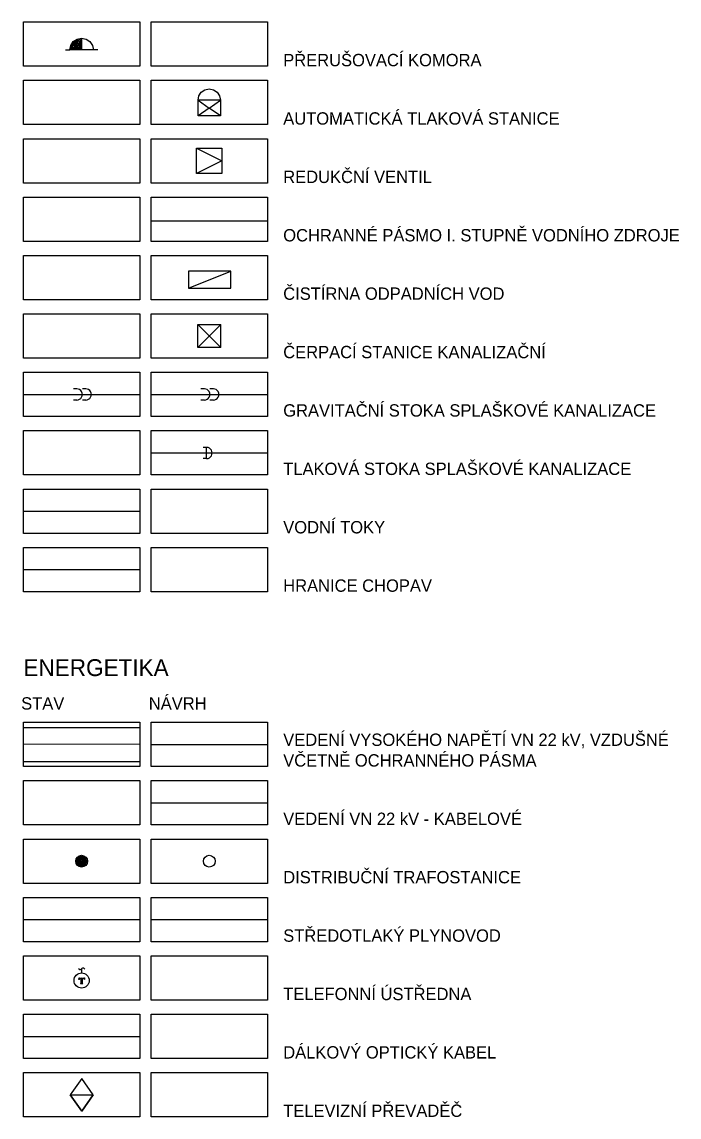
# Model space of a CAD drawing. Extents: x -439236 to -436242, y -1130161 to -1121098.
# Drawn here: x -439126 to -438541, y -1130047 to -1129071 of the extents above; entities that cross this region are included whole.
import ezdxf

# ---------------------------------------------------------------- set-up
doc = ezdxf.new("R2010")
doc.units = 0
for name, color, linetype in [('13861012_venkovní vedení elektrické sítě VN 1-35 kV_Stav', 7, 'Continuous'), ('14250012_plynovod STL_Stav', 7, 'Continuous'), ('14801013_OP vedení elektrické sítě_Stav', 7, 'Continuous'), ('Trafostanice', 7, 'Continuous'), ('Vrstva 1', 7, 'Continuous'), ('Vrstva 10', 7, 'Continuous'), ('Vrstva 11', 7, 'Continuous'), ('Vrstva 13', 7, 'Continuous'), ('Vrstva 19', 7, 'Continuous'), ('Vrstva 27', 7, 'Continuous'), ('Vrstva 33', 7, 'Continuous'), ('Vrstva 34', 7, 'Continuous'), ('Vrstva 36', 7, 'Continuous'), ('Vrstva 39', 7, 'Continuous'), ('Vrstva 46', 7, 'Continuous'), ('Vrstva 57', 7, 'Continuous'), ('Vrstva 58', 7, 'Continuous'), ('Vrstva 59', 7, 'Continuous'), ('WT - vodni a vodnich toku', 7, 'Continuous')]:
    doc.layers.add(name, color=color, linetype=linetype)

msp = doc.modelspace()

# ---------------------------------------------------------------- linework, layer by layer
at = {"layer": '13861012_venkovní vedení elektrické sítě VN 1-35 kV_Stav'}
msp.add_line((-439011.28, -1129715.01), (-438907.66, -1129715.01), dxfattribs=at)
msp.add_lwpolyline([(-439021.28, -1129714.91), (-439124.89, -1129715.12)], dxfattribs=at)
at = {"layer": '14250012_plynovod STL_Stav'}
for p, q in [((-439124.89, -1129871.07), (-439021.28, -1129871.07)), ((-439011.28, -1129871.07), (-438907.66, -1129871.07))]:
    msp.add_line(p, q, dxfattribs=at)
at = {"layer": '14801013_OP vedení elektrické sítě_Stav'}
for p, q in [((-439124.89, -1129699.91), (-439021.28, -1129699.91)), ((-439021.28, -1129730.5), (-439124.89, -1129730.5))]:
    msp.add_line(p, q, dxfattribs=at)
at = {"layer": 'Trafostanice'}
for radius in [5.25, 4.55, 3.85, 3.15, 2.45, 1.75, 1.05, 0.35]:
    msp.add_circle((-439073.09, -1129819.05), radius, dxfattribs=at)
at = {"layer": 'Vrstva 1'}
for points in [[(-439124.89, -1129071.38), (-439021.28, -1129071.38), (-439021.28, -1129071.38), (-439021.28, -1129110.89), (-439124.89, -1129110.89)], [(-439011.28, -1129071.38), (-438907.66, -1129071.38), (-438907.66, -1129110.89), (-439011.28, -1129110.89)], [(-439124.89, -1129123.4), (-439021.28, -1129123.4), (-439021.28, -1129123.4), (-439021.28, -1129162.91), (-439124.89, -1129162.91)], [(-439011.28, -1129123.4), (-438907.66, -1129123.4), (-438907.66, -1129162.91), (-439011.28, -1129162.91)], [(-439124.89, -1129175.42), (-439021.28, -1129175.42), (-439021.28, -1129175.42), (-439021.28, -1129214.92), (-439124.89, -1129214.92)], [(-439011.28, -1129175.42), (-438907.66, -1129175.42), (-438907.66, -1129214.92), (-439011.28, -1129214.92)], [(-439124.89, -1129227.44), (-439021.28, -1129227.44), (-439021.28, -1129227.44), (-439021.28, -1129266.94), (-439124.89, -1129266.94)], [(-439011.28, -1129227.44), (-438907.66, -1129227.44), (-438907.66, -1129266.94), (-439011.28, -1129266.94)], [(-439124.89, -1129279.46), (-439021.28, -1129279.46), (-439021.28, -1129279.46), (-439021.28, -1129318.96), (-439124.89, -1129318.96)], [(-439011.28, -1129279.46), (-438907.66, -1129279.46), (-438907.66, -1129318.96), (-439011.28, -1129318.96)], [(-439124.89, -1129331.48), (-439021.28, -1129331.48), (-439021.28, -1129331.48), (-439021.28, -1129370.98), (-439124.89, -1129370.98)], [(-439011.28, -1129331.48), (-438907.66, -1129331.48), (-438907.66, -1129370.98), (-439011.28, -1129370.98)], [(-439124.89, -1129383.49), (-439021.28, -1129383.49), (-439021.28, -1129383.49), (-439021.28, -1129423), (-439124.89, -1129423)], [(-439011.28, -1129383.49), (-438907.66, -1129383.49), (-438907.66, -1129423), (-439011.28, -1129423)], [(-439124.89, -1129435.51), (-439021.28, -1129435.51), (-439021.28, -1129435.51), (-439021.28, -1129475.02), (-439124.89, -1129475.02)], [(-439011.28, -1129435.51), (-438907.66, -1129435.51), (-438907.66, -1129475.02), (-439011.28, -1129475.02)], [(-439124.89, -1129487.53), (-439021.28, -1129487.53), (-439021.28, -1129487.53), (-439021.28, -1129527.03), (-439124.89, -1129527.03)], [(-439011.28, -1129487.53), (-438907.66, -1129487.53), (-438907.66, -1129527.03), (-439011.28, -1129527.03)], [(-439124.89, -1129539.55), (-439021.28, -1129539.55), (-439021.28, -1129539.55), (-439021.28, -1129579.05), (-439124.89, -1129579.05)], [(-439011.28, -1129539.55), (-438907.66, -1129539.55), (-438907.66, -1129579.05), (-439011.28, -1129579.05)], [(-439124.89, -1129695.26), (-439021.28, -1129695.26), (-439021.28, -1129695.26), (-439021.28, -1129734.77), (-439124.89, -1129734.77)], [(-439011.28, -1129695.26), (-438907.66, -1129695.26), (-438907.66, -1129695.26), (-438907.66, -1129734.77), (-439011.28, -1129734.77)], [(-439124.89, -1129747.28), (-439021.28, -1129747.28), (-439021.28, -1129747.28), (-439021.28, -1129786.78), (-439124.89, -1129786.78)], [(-439011.28, -1129747.28), (-438907.66, -1129747.28), (-438907.66, -1129786.78), (-439011.28, -1129786.78)], [(-439124.89, -1129799.3), (-439021.28, -1129799.3), (-439021.28, -1129799.3), (-439021.28, -1129838.8), (-439124.89, -1129838.8)], [(-439011.28, -1129799.3), (-438907.66, -1129799.3), (-438907.66, -1129838.8), (-439011.28, -1129838.8)], [(-439124.89, -1129851.32), (-439021.28, -1129851.32), (-439021.28, -1129851.32), (-439021.28, -1129890.82), (-439124.89, -1129890.82)], [(-439011.28, -1129851.32), (-438907.66, -1129851.32), (-438907.66, -1129890.82), (-439011.28, -1129890.82)], [(-439124.89, -1129903.33), (-439021.28, -1129903.33), (-439021.28, -1129903.33), (-439021.28, -1129942.84), (-439124.89, -1129942.84)], [(-439011.28, -1129903.33), (-438907.66, -1129903.33), (-438907.66, -1129942.84), (-439011.28, -1129942.84)], [(-439124.89, -1129955.35), (-439021.28, -1129955.35), (-439021.28, -1129955.35), (-439021.28, -1129994.86), (-439124.89, -1129994.86)], [(-439011.28, -1129955.35), (-438907.66, -1129955.35), (-438907.66, -1129994.86), (-439011.28, -1129994.86)], [(-439124.89, -1130007.37), (-439021.28, -1130007.37), (-439021.28, -1130007.37), (-439021.28, -1130046.88), (-439124.89, -1130046.88)], [(-439011.28, -1130007.37), (-438907.66, -1130007.37), (-438907.66, -1130046.88), (-439011.28, -1130046.88)]]:
    msp.add_lwpolyline(points, close=True, dxfattribs=at)
at = {"layer": 'Vrstva 10'}
msp.add_line((-438949.47, -1129155.15), (-438969.47, -1129155.15), dxfattribs=at)
for points in [[(-438969.47, -1129141.15), (-438968.71, -1129137.33), (-438966.54, -1129134.08), (-438963.3, -1129131.92), (-438959.47, -1129131.15), (-438955.64, -1129131.92), (-438952.4, -1129134.08), (-438950.23, -1129137.33), (-438949.47, -1129141.15)], [(-438969.47, -1129141.15), (-438959.47, -1129148.15), (-438969.47, -1129155.15)], [(-438949.47, -1129141.15), (-438949.47, -1129155.15), (-438959.47, -1129148.15)], [(-438970.77, -1129183.87), (-438948.17, -1129195.17), (-438970.77, -1129206.47)]]:
    msp.add_lwpolyline(points, close=True, dxfattribs=at)
msp.add_lwpolyline([(-438970.77, -1129183.87), (-438948.17, -1129183.87), (-438948.17, -1129195.17), (-438948.17, -1129206.47), (-438970.77, -1129206.47)], dxfattribs=at)
at = {"layer": 'Vrstva 11'}
for p, q in [((-439087.49, -1129096.36), (-439083.54, -1129096.36)), ((-439058.69, -1129096.36), (-439062.64, -1129096.36))]:
    msp.add_line(p, q, dxfattribs=at)
for points in [[(-439083.54, -1129096.36), (-439082.74, -1129092.36), (-439080.48, -1129088.97), (-439077.09, -1129086.71), (-439073.09, -1129085.91), (-439073.09, -1129096.36)], [(-439082.32, -1129095.36), (-439081.8, -1129092.75), (-439079.75, -1129089.69), (-439076.7, -1129087.65), (-439074.09, -1129087.13), (-439074.09, -1129095.36)], [(-439081.1, -1129094.36), (-439080.86, -1129093.14), (-439079.03, -1129090.41), (-439076.3, -1129088.59), (-439075.09, -1129088.35), (-439075.09, -1129094.36)], [(-439078.31, -1129091.13), (-439076.09, -1129089.65), (-439076.09, -1129093.36), (-439079.8, -1129093.36)], [(-439077.93, -1129092.36), (-439077.59, -1129091.86), (-439077.09, -1129091.52), (-439077.09, -1129092.36)]]:
    msp.add_lwpolyline(points, close=True, dxfattribs=at)
msp.add_lwpolyline([(-439073.09, -1129085.91), (-439069.09, -1129086.71), (-439065.7, -1129088.97), (-439063.43, -1129092.36), (-439062.64, -1129096.36), (-439073.09, -1129096.36)], dxfattribs=at)
at = {"layer": 'Vrstva 13'}
msp.add_line((-439011.28, -1129767.03), (-438907.66, -1129767.03), dxfattribs=at)
at = {"layer": 'Vrstva 19'}
msp.add_circle((-438959.47, -1129819.05), 5.25, dxfattribs=at)
at = {"layer": 'Vrstva 27'}
msp.add_line((-439011.28, -1129248.56), (-438907.66, -1129248.56), dxfattribs=at)
at = {"layer": 'Vrstva 33'}
for p, q in [((-438969.71, -1129340.91), (-438949.23, -1129340.91)), ((-438969.71, -1129340.91), (-438949.23, -1129361.55)), ((-438969.71, -1129361.55), (-438969.71, -1129340.91)), ((-438949.23, -1129340.91), (-438959.47, -1129351.23)), ((-438949.23, -1129361.55), (-438949.23, -1129340.91)), ((-438959.47, -1129351.23), (-438969.71, -1129361.55)), ((-438949.23, -1129361.55), (-438969.71, -1129361.55))]:
    msp.add_line(p, q, dxfattribs=at)
msp.add_lwpolyline([(-438978.08, -1129308.53), (-438940.3, -1129308.53), (-438940.3, -1129293.35), (-438978.08, -1129293.35)], close=True, dxfattribs=at)
msp.add_lwpolyline([(-438978.08, -1129308.53), (-438940.3, -1129293.35)], dxfattribs=at)
at = {"layer": 'Vrstva 34'}
msp.add_line((-439124.89, -1129403.25), (-439021.28, -1129403.25), dxfattribs=at)
at = {"layer": 'Vrstva 36'}
for p, q in [((-439011.28, -1129403.25), (-438907.66, -1129403.25)), ((-439011.28, -1129455.26), (-438907.66, -1129455.26))]:
    msp.add_line(p, q, dxfattribs=at)
at = {"layer": 'Vrstva 39'}
for p, q in [((-439077.43, -1129398.26), (-439080.43, -1129398.26)), ((-439069.43, -1129398.26), (-439072.43, -1129398.26)), ((-438963.81, -1129398.26), (-438966.81, -1129398.26)), ((-438955.81, -1129398.26), (-438958.81, -1129398.26)), ((-439077.43, -1129408.26), (-439080.43, -1129408.26)), ((-439069.43, -1129408.26), (-439072.43, -1129408.26)), ((-438963.81, -1129408.26), (-438966.81, -1129408.26)), ((-438955.81, -1129408.26), (-438958.81, -1129408.26)), ((-438961.85, -1129450.41), (-438964.85, -1129450.41)), ((-438961.85, -1129460.41), (-438961.85, -1129450.41)), ((-438961.85, -1129460.41), (-438964.85, -1129460.41))]:
    msp.add_line(p, q, dxfattribs=at)
for centre, start in [((-439077.43, -1129403.26), 270), ((-439069.43, -1129403.26), 270), ((-438963.81, -1129403.26), 270), ((-438955.81, -1129403.26), 270), ((-438961.85, -1129455.41), 270.00038)]:
    msp.add_arc(centre, 5, start, 90.00107, dxfattribs=at)
at = {"layer": 'Vrstva 46'}
msp.add_line((-439124.89, -1129559.3), (-439021.28, -1129559.3), dxfattribs=at)
at = {"layer": 'Vrstva 57'}
for p, q in [((-439073.09, -1129914.87), (-439073.09, -1129918.62)), ((-439075.16, -1129924.18), (-439075.5, -1129923.85)), ((-439074.83, -1129923.82), (-439075.44, -1129923.21)), ((-439074.48, -1129923.46), (-439074.8, -1129923.13)), ((-439073.77, -1129923.46), (-439074.1, -1129923.13)), ((-439072.63, -1129923.89), (-439073.39, -1129923.13)), ((-439072.63, -1129924.6), (-439073.36, -1129923.87)), ((-439072.63, -1129925.31), (-439073.36, -1129924.58)), ((-439072.63, -1129926.01), (-439073.36, -1129925.28)), ((-439072.63, -1129926.72), (-439073.36, -1129925.99)), ((-439072.35, -1129923.46), (-439072.68, -1129923.13)), ((-439071.65, -1129923.46), (-439071.98, -1129923.13)), ((-439070.48, -1129923.92), (-439071.27, -1129923.13)), ((-439070.56, -1129923.13), (-439070.67, -1129923.02)), ((-439073.81, -1129928.37), (-439074.04, -1129928.14)), ((-439073.1, -1129928.37), (-439073.65, -1129927.82)), ((-439072.63, -1129927.43), (-439073.36, -1129926.7)), ((-439072.39, -1129928.37), (-439073.36, -1129927.41))]:
    msp.add_line(p, q, dxfattribs=at)
msp.add_lwpolyline([(-439075.99, -1129914.42), (-439075.48, -1129915.06), (-439074.83, -1129915.56), (-439074.43, -1129915.68), (-439074.03, -1129915.61), (-439073.51, -1129915.3), (-439073.09, -1129914.87), (-439072.66, -1129914.44), (-439072.15, -1129914.13), (-439071.74, -1129914.06), (-439071.35, -1129914.18), (-439070.7, -1129914.68), (-439070.18, -1129915.31)], dxfattribs=at)
msp.add_lwpolyline([(-439070.57, -1129923.02), (-439070.43, -1129924.41), (-439070.61, -1129924.41), (-439071.49, -1129923.46), (-439072.63, -1129923.46), (-439072.63, -1129927.58), (-439071.88, -1129928.19), (-439071.88, -1129928.37), (-439074.1, -1129928.37), (-439074.1, -1129928.19), (-439073.36, -1129927.58), (-439073.36, -1129923.46), (-439074.5, -1129923.46), (-439075.37, -1129924.41), (-439075.56, -1129924.41), (-439075.42, -1129923.02), (-439075.23, -1129923.02), (-439074.91, -1129923.13), (-439071.08, -1129923.13), (-439070.76, -1129923.02)], close=True, dxfattribs=at)
msp.add_circle((-439073.09, -1129925.37), 6.75, dxfattribs=at)
at = {"layer": 'Vrstva 58'}
msp.add_line((-439124.89, -1129975.1), (-439021.28, -1129975.1), dxfattribs=at)
at = {"layer": 'Vrstva 59'}
for points in [[(-439072.9, -1130012.53), (-439083.33, -1130027.08), (-439072.9, -1130041.71), (-439062.84, -1130027.08)], [(-439083.33, -1130027.08), (-439062.84, -1130027.08), (-439072.9, -1130041.71)]]:
    msp.add_lwpolyline(points, close=True, dxfattribs=at)
at = {"layer": 'WT - vodni a vodnich toku'}
msp.add_line((-439124.89, -1129507.28), (-439021.28, -1129507.28), dxfattribs=at)

# ---------------------------------------------------------------- texts
at = {"layer": 'Vrstva 1'}
for s, height, p in [('PŘERUŠOVACÍ KOMORA', 11, (-438893.61, -1129110.89)), ('AUTOMATICKÁ TLAKOVÁ STANICE', 11, (-438893.61, -1129162.91)), ('REDUKČNÍ VENTIL', 11, (-438893.61, -1129214.92)), ('OCHRANNÉ PÁSMO I. STUPNĚ VODNÍHO ZDROJE', 11, (-438893.61, -1129266.94)), ('ČISTÍRNA ODPADNÍCH VOD', 11, (-438893.61, -1129318.96)), ('ČERPACÍ STANICE KANALIZAČNÍ', 11, (-438893.61, -1129370.98)), ('GRAVITAČNÍ STOKA SPLAŠKOVÉ KANALIZACE', 11, (-438893.61, -1129423)), ('TLAKOVÁ STOKA SPLAŠKOVÉ KANALIZACE', 11, (-438893.61, -1129475.02)), ('VODNÍ TOKY', 11, (-438893.61, -1129527.03)), ('HRANICE CHOPAV', 11, (-438893.61, -1129579.05)), ('ENERGETIKA', 15, (-439124.89, -1129654.14)), ('NÁVRH', 11, (-439013.3, -1129684.01)), ('STAV', 11, (-439126.91, -1129684.01)), ('VEDENÍ VYSOKÉHO NAPĚTÍ VN 22 kV, VZDUŠNÉ', 11, (-438893.61, -1129716.35)), ('VČETNĚ OCHRANNÉHO PÁSMA', 11, (-438893.61, -1129734.77)), ('VEDENÍ VN 22 kV - KABELOVÉ', 11, (-438893.61, -1129786.78)), ('DISTRIBUČNÍ TRAFOSTANICE', 11, (-438893.61, -1129838.8)), ('STŘEDOTLAKÝ PLYNOVOD', 11, (-438893.61, -1129890.82)), ('TELEFONNÍ ÚSTŘEDNA', 11, (-438893.61, -1129942.84)), ('DÁLKOVÝ OPTICKÝ KABEL', 11, (-438893.61, -1129994.86)), ('TELEVIZNÍ PŘEVADĚČ', 11, (-438893.61, -1130046.88))]:
    msp.add_text(s, height=height, dxfattribs=at).set_placement(p)

doc.saveas('drawing.dxf')
